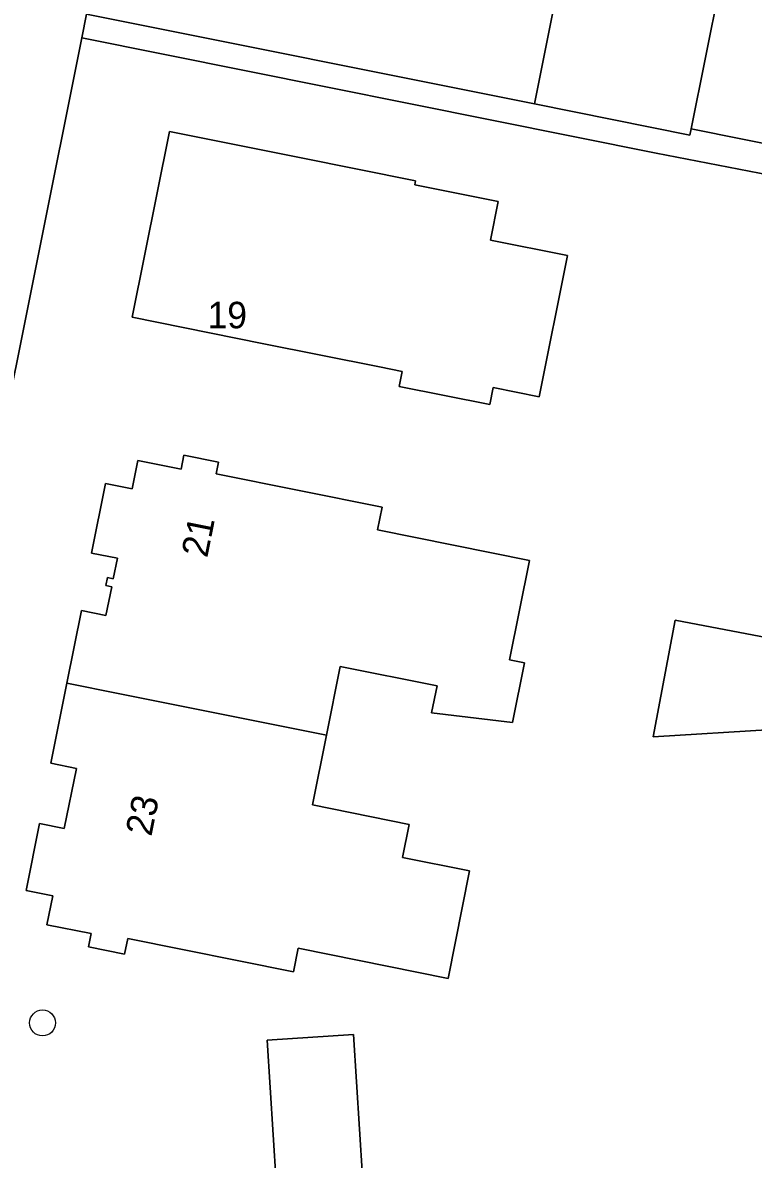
# Model space of a CAD drawing. Extents: x 161772 to 163126, y 383092 to 383917.
# Drawn here: x 162253.38 to 162280.92, y 383665.1 to 383707.95 of the extents above; entities that cross this region are included whole.
import ezdxf

# ---------------------------------------------------------------- set-up
doc = ezdxf.new("R2010")
doc.units = 0
for name, color, linetype in [('IMGEO_Boom', 7, 'Continuous'), ('IMGEO_Erf', 7, 'Continuous'), ('IMGEO_Pand', 7, 'Continuous'), ('IMGEO_Pand_nummerreeks', 7, 'Continuous'), ('IMGEO_Voetpad_open', 7, 'Continuous')]:
    doc.layers.add(name, color=color, linetype=linetype)

msp = doc.modelspace()

# ---------------------------------------------------------------- linework, layer by layer
at = {"layer": 'IMGEO_Boom'}
msp.add_circle((162254.126, 383670.243), 0.489, dxfattribs=at)
at = {"layer": 'IMGEO_Erf'}
for points in [[(162280.199, 383712.031), (162278.578, 383703.948), (162284.515, 383702.757)], [(162255.783, 383708.274), (162272.677, 383704.886), (162273.409, 383708.533)], [(162285.84, 383701.374), (162277.263, 383703.035), (162255.603, 383707.378), (162240.556, 383632.345)]]:
    msp.add_lwpolyline(points, dxfattribs=at)
for points in [[(162271.309, 383701.207), (162271.018, 383699.753), (162273.924, 383699.17), (162272.856, 383693.843), (162271.118, 383694.192), (162270.99, 383693.552), (162267.567, 383694.238), (162267.68, 383694.801), (162266.832, 383694.971), (162262.405, 383695.859), (162257.502, 383696.842), (162258.908, 383703.853), (162263.811, 383702.869), (162268.193, 383701.99), (162268.162, 383701.838)], [(162269.417, 383671.922), (162263.768, 383673.055), (162263.59, 383672.169), (162257.338, 383673.423), (162257.221, 383672.84), (162255.856, 383673.114), (162255.955, 383673.608), (162254.293, 383673.941), (162254.513, 383675.034), (162253.503, 383675.237), (162254.009, 383677.756), (162254.946, 383677.568), (162255.401, 383679.836), (162254.441, 383680.029), (162255.047, 383683.053), (162255.595, 383685.789), (162256.516, 383685.604), (162256.733, 383686.684), (162256.517, 383686.728), (162256.578, 383687.031), (162256.793, 383686.988), (162256.948, 383687.76), (162255.973, 383687.955), (162256.5, 383690.583), (162257.509, 383690.381), (162257.724, 383691.449), (162259.354, 383691.122), (162259.458, 383691.641), (162260.762, 383691.379), (162260.673, 383690.936), (162266.927, 383689.681), (162266.756, 383688.825), (162272.486, 383687.676), (162271.735, 383683.929), (162272.292, 383683.818), (162271.84, 383681.562), (162268.794, 383681.931), (162268.999, 383682.953), (162265.353, 383683.684), (162264.833, 383681.092), (162264.305, 383678.459), (162267.954, 383677.727), (162267.704, 383676.478), (162270.23, 383675.972)], [(162281.996, 383684.661), (162281.636, 383681.302), (162277.15, 383681.032), (162277.984, 383685.427)], [(162266.193, 383664.449), (162262.933, 383664.24), (162262.589, 383669.595), (162265.848, 383669.805)]]:
    msp.add_lwpolyline(points, close=True, dxfattribs=at)
at = {"layer": 'IMGEO_Pand'}
for points in [[(162280.199, 383712.031), (162277.979, 383712.476), (162274.016, 383713.271), (162274.041, 383713.396), (162262.008, 383715.847), (162261.793, 383714.777), (162260.959, 383714.495), (162260.629, 383712.852), (162261.224, 383711.958), (162261.035, 383711.015), (162265.938, 383710.032), (162270.264, 383709.164), (162273.079, 383708.599), (162273.409, 383708.533), (162272.677, 383704.886), (162278.53, 383703.711), (162278.578, 383703.948)], [(162263.811, 383702.869), (162258.908, 383703.853), (162257.502, 383696.842), (162262.405, 383695.859), (162266.832, 383694.971), (162267.68, 383694.801), (162267.567, 383694.238), (162270.99, 383693.552), (162271.118, 383694.192), (162272.856, 383693.843), (162273.924, 383699.17), (162271.018, 383699.753), (162271.309, 383701.207), (162268.162, 383701.838), (162268.193, 383701.99)], [(162272.486, 383687.676), (162266.756, 383688.825), (162266.927, 383689.681), (162260.673, 383690.936), (162260.762, 383691.379), (162259.458, 383691.641), (162259.354, 383691.122), (162257.724, 383691.449), (162257.509, 383690.381), (162256.5, 383690.583), (162255.973, 383687.955), (162256.948, 383687.76), (162256.793, 383686.988), (162256.578, 383687.031), (162256.517, 383686.728), (162256.733, 383686.684), (162256.516, 383685.604), (162255.595, 383685.789), (162255.047, 383683.053), (162257.039, 383682.655), (162264.833, 383681.092), (162265.353, 383683.684), (162268.999, 383682.953), (162268.794, 383681.931), (162271.84, 383681.562), (162272.292, 383683.818), (162271.735, 383683.929)], [(162281.636, 383681.302), (162281.996, 383684.661), (162277.984, 383685.427), (162277.15, 383681.032)], [(162257.039, 383682.655), (162255.047, 383683.053), (162254.441, 383680.029), (162255.401, 383679.836), (162254.946, 383677.568), (162254.009, 383677.756), (162253.503, 383675.237), (162254.513, 383675.034), (162254.293, 383673.941), (162255.955, 383673.608), (162255.856, 383673.114), (162257.221, 383672.84), (162257.338, 383673.423), (162263.59, 383672.169), (162263.768, 383673.055), (162269.417, 383671.922), (162270.23, 383675.972), (162267.704, 383676.478), (162267.954, 383677.727), (162264.305, 383678.459), (162264.833, 383681.092)], [(162262.933, 383664.24), (162266.193, 383664.449), (162265.848, 383669.805), (162262.589, 383669.595)]]:
    msp.add_lwpolyline(points, close=True, dxfattribs=at)
at = {"layer": 'IMGEO_Voetpad_open'}
for points in [[(162255.603, 383707.378), (162255.783, 383708.274), (162264.15, 383750), (162269.552, 383776.935), (162269.728, 383777.815), (162270.877, 383783.542), (162272.117, 383789.029)], [(162237.463, 383629.88), (162241.527, 383630.611), (162240.556, 383632.345), (162255.603, 383707.378)]]:
    msp.add_lwpolyline(points, dxfattribs=at)
msp.add_lwpolyline([(162287.722, 383710.711), (162287.776, 383711.032), (162286.234, 383711.335), (162284.601, 383703.204), (162284.515, 383702.757), (162278.578, 383703.948), (162278.53, 383703.711), (162272.677, 383704.886), (162255.783, 383708.274), (162255.603, 383707.378), (162277.263, 383703.035), (162285.84, 383701.374), (162285.922, 383701.797)], close=True, dxfattribs=at)

# ---------------------------------------------------------------- texts
at = {"layer": 'IMGEO_Pand_nummerreeks'}
msp.add_text('19', height=1, dxfattribs=at).set_placement((162260.347, 383696.428))
for s, rotation, p in [('21', 78.7817, (162260.335, 383687.751)), ('23', 78.6561, (162258.227, 383677.247))]:
    msp.add_text(s, height=1, rotation=rotation, dxfattribs=at).set_placement(p)

doc.saveas('drawing.dxf')
